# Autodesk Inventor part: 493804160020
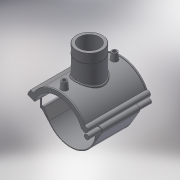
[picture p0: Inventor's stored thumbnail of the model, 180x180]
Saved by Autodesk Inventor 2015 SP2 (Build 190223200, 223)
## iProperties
Created: 2017-07
Part Number: 493804160020
Material: Generic
Description: PLASSON TRANSITION SADDLE 160-2"
Document SubType Name: Modeling
Designer: KIM
Density: 1 g/cm^3
Appearance: Default
Author: KIM
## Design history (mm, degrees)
derived "493804.ipt"
feature "Solid1::493804.ipt"
tag "TaggingFeature1"
body "Solid1"
other parameters: "B_" = 176, "H_" = 76, "L_" = 176, "d_t" = 6, "G_" = 56.656, "d148" = 2.4, "d160" = 2.4, "d169" = 2.4, "d192" = 4.8, "d1" = 184, "d2" = 228.8, "d4" = 176, "d5" = 0, "d6" = 0.1, "d8" = 0, "d19" = 6, "d20" = 6, "d21" = 105.6, "d23" = 0, "d24" = 52.8, "d26" = 0, "d27" = 3, "d28" = 3, "d29" = 3, "d30" = 53.33333, "d31" = 6, "d32" = 0, "d33" = 0, "d34" = 0.6, "d40" = 95.68, "d41" = 79.3184, "d43" = 0, "d45" = 0, "d47" = 168, "d48" = 73.6528, "d50" = 0, "d70" = 15, "d72" = 0, "d73" = 6, "d75" = 5, "d76" = 0, "d77" = 8, "d79" = 15, "d80" = 70.4, "d82" = 5 deg, "d84" = 4, "d85" = 14, "d86" = 0, "d87" = 3, "d88" = 0, "d89" = 1, "d90" = 1, "d91" = 140.8, "d92" = 0, "d93" = 0.5, "d94" = 84.21053, "d96" = 187.68, "d97" = 3.52, "d98" = 0, "d102" = 1.69968, "d103" = 56.656, "d104" = 45.6, "d105" = 0, "d106" = 45.3248, "d108" = 0, "d109" = -25.33333, "d111" = 0.5, "d112" = 0.5, "d113" = 0, "d114" = 0.5, "d117" = 0.56656, "d120" = 140 deg, "d121" = 24.228, "d122" = 20 deg, "d123" = 368, "d124" = 110.4, "d126" = 0, "d143" = 164.8, "d145" = 18.46154, "d149" = 2.4, "d150" = 20.30769, "d153" = 176, "d154" = 0, "d156" = 92, "d157" = 160 deg, "d159" = 4.8, "d161" = 2.4, "d162" = 105.6, "d163" = 0, "d167" = 16, "d168" = 89.7561, "d170" = 2.4, "d172" = 0, "d173" = 1, "d176" = 20 deg, "d177" = 11.2, "d178" = 24, "d180" = 0, "d183" = 9.6, "d184" = 8.96, "d185" = 57.2, "d186" = 57.2, "d187" = 92, "d188" = 7.2, "d189" = 11.2, "d190" = 0, "d191" = 110.4, "d193" = 4.8, "d194" = 4.4, "d195" = 90 deg, "d197" = 0, "d199" = 0
